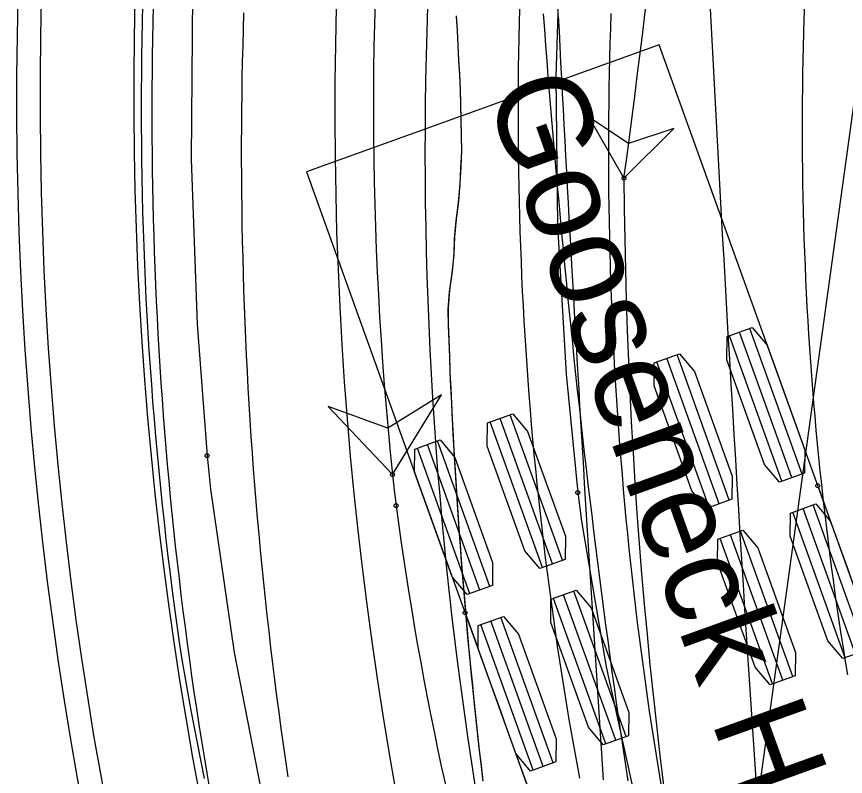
# Model space of a CAD drawing. Extents: x -14 to 1565148, y -25 to 642856.
# Drawn here: x 1564752.49 to 1564770.18, y 636470.57 to 636486.78 of the extents above; entities that cross this region are included whole.
import ezdxf

# ---------------------------------------------------------------- set-up
doc = ezdxf.new("R2010")
doc.units = 0
for name, color, linetype in [('CM_Corridor_Conceptual', 7, 'Continuous'), ('DR_P_Headwall', 7, 'Continuous'), ('GE_P_Alignment_100_Stations', 7, 'Continuous'), ('PV_P_EOP', 7, 'Continuous'), ('PV_X_EOP', 7, 'Continuous'), ('TR_Turning_Path22', 7, 'Continuous'), ('TR_Turning_Path28', 7, 'Continuous'), ('TR_Turning_Path28 - Copy-1', 7, 'Continuous')]:
    doc.layers.add(name, color=color, linetype=linetype)

msp = doc.modelspace()

# ---------------------------------------------------------------- linework, layer by layer
at = {"layer": 'CM_Corridor_Conceptual'}
for p, q in [((1564766.204, 636486.176), (1564758.676, 636483.468)), ((1564778.392, 636452.302), (1564766.204, 636486.176)), ((1564758.676, 636483.468), (1564770.864, 636449.594)), ((1564769.255, 636477.018), (1564768.138, 636480.123)), ((1564768.824, 636476.863), (1564767.707, 636479.968)), ((1564769.039, 636476.941), (1564767.922, 636480.046)), ((1564767.702, 636476.46), (1564766.585, 636479.565)), ((1564767.271, 636476.305), (1564766.154, 636479.41)), ((1564767.487, 636476.382), (1564766.37, 636479.487)), ((1564763.711, 636475.024), (1564762.594, 636478.129)), ((1564763.927, 636475.101), (1564762.81, 636478.206)), ((1564764.143, 636475.179), (1564763.025, 636478.284)), ((1564762.374, 636474.543), (1564761.257, 636477.648)), ((1564762.59, 636474.62), (1564761.473, 636477.725)), ((1564762.159, 636474.465), (1564761.042, 636477.57)), ((1564770.609, 636473.255), (1564769.492, 636476.36)), ((1564770.178, 636473.099), (1564769.061, 636476.204)), ((1564770.394, 636473.177), (1564769.276, 636476.282)), ((1564768.625, 636472.541), (1564767.508, 636475.646)), ((1564768.841, 636472.618), (1564767.724, 636475.723)), ((1564769.057, 636472.696), (1564767.939, 636475.801)), ((1564765.281, 636471.337), (1564764.164, 636474.443)), ((1564765.497, 636471.415), (1564764.38, 636474.52)), ((1564765.066, 636471.26), (1564763.948, 636474.365)), ((1564763.729, 636470.779), (1564762.611, 636473.884)), ((1564763.944, 636470.856), (1564762.827, 636473.962)), ((1564763.513, 636470.701), (1564762.396, 636473.806))]:
    msp.add_line(p, q, dxfattribs=at)
for points in [[(1564769.309, 636477.038), (1564768.77, 636476.844), (1564768.452, 636477.22), (1564767.647, 636479.456), (1564767.653, 636479.949), (1564768.191, 636480.143), (1564768.51, 636479.766), (1564769.314, 636477.531)], [(1564767.756, 636476.479), (1564767.218, 636476.285), (1564766.899, 636476.662), (1564766.095, 636478.897), (1564766.101, 636479.39), (1564766.639, 636479.584), (1564766.957, 636479.208), (1564767.762, 636476.972)], [(1564764.196, 636475.198), (1564763.658, 636475.004), (1564763.339, 636475.381), (1564762.535, 636477.616), (1564762.541, 636478.11), (1564763.079, 636478.303), (1564763.397, 636477.927), (1564764.202, 636475.691)], [(1564762.644, 636474.639), (1564762.105, 636474.446), (1564761.787, 636474.822), (1564760.982, 636477.058), (1564760.988, 636477.551), (1564761.526, 636477.745), (1564761.845, 636477.368), (1564762.649, 636475.133)], [(1564770.663, 636473.274), (1564770.125, 636473.08), (1564769.806, 636473.456), (1564769.002, 636475.692), (1564769.007, 636476.185), (1564769.546, 636476.379), (1564769.864, 636476.003), (1564770.669, 636473.767)], [(1564769.11, 636472.715), (1564768.572, 636472.521), (1564768.253, 636472.898), (1564767.449, 636475.134), (1564767.455, 636475.627), (1564767.993, 636475.82), (1564768.312, 636475.444), (1564769.116, 636473.208)], [(1564765.55, 636471.434), (1564765.012, 636471.241), (1564764.693, 636471.617), (1564763.889, 636473.853), (1564763.895, 636474.346), (1564764.433, 636474.539), (1564764.752, 636474.163), (1564765.556, 636471.927)], [(1564763.998, 636470.876), (1564763.46, 636470.682), (1564763.141, 636471.058), (1564762.337, 636473.294), (1564762.342, 636473.787), (1564762.88, 636473.981), (1564763.199, 636473.604), (1564764.003, 636471.369)]]:
    msp.add_lwpolyline(points, close=True, dxfattribs=at)
for points in [[(1564769.589, 636476.767), (1564769.702, 636476.454), (1564769.814, 636476.141), (1564769.927, 636475.828), (1564770.039, 636475.515), (1564770.152, 636475.202), (1564770.265, 636474.89)], [(1564762.062, 636474.058), (1564762.174, 636473.745), (1564762.287, 636473.432), (1564762.399, 636473.12), (1564762.512, 636472.807), (1564762.624, 636472.494), (1564762.737, 636472.181), (1564762.85, 636471.868), (1564762.962, 636471.555), (1564763.075, 636471.242), (1564763.187, 636470.93), (1564763.3, 636470.617), (1564763.413, 636470.304)]]:
    msp.add_lwpolyline(points, dxfattribs=at)
for centre in [(1564769.589, 636476.767), (1564762.062, 636474.058)]:
    msp.add_circle(centre, 0.0417, dxfattribs=at)
at = {"layer": 'DR_P_Headwall'}
for points in [[(1564762.441, 636470.512), (1564762.403, 636470.845), (1564762.365, 636471.177), (1564762.328, 636471.51), (1564762.292, 636471.843), (1564762.257, 636472.177), (1564762.223, 636472.51), (1564762.19, 636472.844), (1564762.158, 636473.178), (1564762.126, 636473.513), (1564762.096, 636473.847), (1564762.067, 636474.182), (1564762.039, 636474.516), (1564762.011, 636474.851), (1564761.985, 636475.186), (1564761.96, 636475.521), (1564761.935, 636475.857), (1564761.912, 636476.192), (1564761.889, 636476.528), (1564761.868, 636476.863), (1564761.847, 636477.199), (1564761.828, 636477.535), (1564761.809, 636477.87), (1564761.792, 636478.206), (1564761.775, 636478.542), (1564761.76, 636478.878), (1564761.745, 636479.214), (1564761.732, 636479.549), (1564761.719, 636479.885), (1564761.707, 636480.221), (1564761.708, 636480.567), (1564761.739, 636480.944), (1564761.79, 636481.341), (1564761.826, 636481.72), (1564761.84, 636482.076), (1564761.876, 636482.453), (1564761.925, 636482.842), (1564761.957, 636483.213), (1564761.976, 636483.569), (1564761.991, 636483.92), (1564761.985, 636484.249), (1564761.98, 636484.579), (1564761.973, 636484.906), (1564761.962, 636485.227), (1564761.947, 636485.544), (1564761.931, 636485.858), (1564761.914, 636486.171), (1564761.897, 636486.483), (1564761.879, 636486.793)], [(1564762.447, 636470.464), (1564762.408, 636470.797), (1564762.37, 636471.13), (1564762.333, 636471.463), (1564762.297, 636471.797), (1564762.261, 636472.131), (1564762.227, 636472.465), (1564762.194, 636472.799), (1564762.162, 636473.134), (1564762.13, 636473.469), (1564762.1, 636473.804), (1564762.07, 636474.139), (1564762.042, 636474.474), (1564762.015, 636474.809), (1564761.988, 636475.145), (1564761.962, 636475.481), (1564761.938, 636475.817), (1564761.914, 636476.153), (1564761.892, 636476.489), (1564761.87, 636476.825), (1564761.85, 636477.161), (1564761.83, 636477.498), (1564761.811, 636477.834), (1564761.794, 636478.171), (1564761.777, 636478.507), (1564761.761, 636478.843), (1564761.746, 636479.18), (1564761.733, 636479.517), (1564761.72, 636479.853), (1564761.708, 636480.189), (1564761.698, 636480.527), (1564761.731, 636480.906), (1564761.786, 636481.307), (1564761.828, 636481.693), (1564761.836, 636482.045), (1564761.871, 636482.422), (1564761.923, 636482.814), (1564761.957, 636483.188), (1564761.972, 636483.542), (1564761.991, 636483.898), (1564761.985, 636484.229), (1564761.98, 636484.559), (1564761.973, 636484.887), (1564761.962, 636485.21), (1564761.948, 636485.528), (1564761.931, 636485.844), (1564761.915, 636486.158), (1564761.897, 636486.472), (1564761.879, 636486.783)], [(1564765.453, 636483.33), (1564766.516, 636484.388), (1564765.552, 636484.073), (1564764.706, 636484.631), (1564765.453, 636483.33)]]:
    msp.add_lwpolyline(points, dxfattribs=at)
msp.add_lwpolyline([(1564765.453, 636483.33), (1564766.516, 636484.388), (1564765.552, 636484.073), (1564764.706, 636484.631)], close=True, dxfattribs=at)
msp.add_circle((1564765.453, 636483.33), 0.0417, dxfattribs=at)
msp.add_circle((1564765.453, 636483.33), 0.0417, dxfattribs=at)
for centre, radius, start, end in [((1564504.01, 636518.53), 263.802, 352.33185, 358.4354), ((1564877.338, 636484.105), 111.888, 180.39704, 201.6728)]:
    msp.add_arc(centre, radius, start, end, dxfattribs=at)
at = {"layer": 'GE_P_Alignment_100_Stations'}
msp.add_line((1564772.301, 636499.036), (1564765.743, 636451.487), dxfattribs=at)
for points in [[(1564756.72, 636493.911), (1564756.427, 636490.771), (1564756.241, 636487.255), (1564756.212, 636483.734), (1564756.339, 636480.216), (1564756.554, 636477.407)], [(1564764.303, 636491.539), (1564764.097, 636488.674), (1564763.996, 636485.499), (1564764.037, 636482.323), (1564764.219, 636479.152), (1564764.466, 636476.623)], [(1564756.497, 636470.522), (1564756.424, 636470.884), (1564756.353, 636471.246), (1564756.283, 636471.609), (1564756.216, 636471.972), (1564756.15, 636472.335), (1564756.086, 636472.699), (1564756.024, 636473.063), (1564755.967, 636473.428), (1564755.914, 636473.793), (1564755.865, 636474.158), (1564755.817, 636474.524), (1564755.77, 636474.89), (1564755.725, 636475.256), (1564755.682, 636475.623), (1564755.641, 636475.989), (1564755.601, 636476.356), (1564755.563, 636476.722), (1564755.527, 636477.089), (1564755.492, 636477.456), (1564755.459, 636477.824), (1564755.428, 636478.191), (1564755.398, 636478.559), (1564755.371, 636478.926), (1564755.344, 636479.294), (1564755.32, 636479.662), (1564755.297, 636480.03), (1564755.276, 636480.398), (1564755.256, 636480.766), (1564755.239, 636481.134), (1564755.223, 636481.502), (1564755.208, 636481.87), (1564755.195, 636482.239), (1564755.184, 636482.607), (1564755.175, 636482.975), (1564755.168, 636483.344), (1564755.162, 636483.712), (1564755.157, 636484.081), (1564755.155, 636484.449), (1564755.154, 636484.818), (1564755.155, 636485.186), (1564755.157, 636485.555), (1564755.162, 636485.923), (1564755.167, 636486.291), (1564755.175, 636486.66), (1564755.184, 636487.028)], [(1564760.511, 636477.005), (1564761.561, 636478.708), (1564760.409, 636478), (1564759.138, 636478.46), (1564760.511, 636477.005)], [(1564756.553, 636477.408), (1564756.629, 636476.696), (1564757.134, 636473.208), (1564757.805, 636469.75), (1564758.638, 636466.328), (1564759.633, 636462.95), (1564760.788, 636459.622), (1564762.1, 636456.353), (1564763.565, 636453.15), (1564763.876, 636452.518)], [(1564760.511, 636477.005), (1564760.546, 636476.674), (1564760.588, 636476.343)], [(1564764.466, 636476.622), (1564764.545, 636476.012), (1564765.072, 636472.905), (1564765.748, 636469.823), (1564766.569, 636466.777), (1564767.534, 636463.773), (1564768.641, 636460.819), (1564769.887, 636457.921), (1564771.269, 636455.086), (1564771.561, 636454.527)]]:
    msp.add_lwpolyline(points, dxfattribs=at)
msp.add_lwpolyline([(1564760.511, 636477.005), (1564761.561, 636478.708), (1564760.409, 636478), (1564759.138, 636478.46)], close=True, dxfattribs=at)
for centre in [(1564756.553, 636477.408), (1564756.554, 636477.407), (1564760.511, 636477.005), (1564760.511, 636477.005), (1564764.466, 636476.623), (1564764.466, 636476.622), (1564760.588, 636476.343), (1564760.588, 636476.343)]:
    msp.add_circle(centre, 0.0417, dxfattribs=at)
for centre, radius, start, end in [((1564835.491, 636484.834), 75.387, 174.25352, 185.96071), ((1564830.196, 636485.568), 70.216, 187.54952, 207.16349)]:
    msp.add_arc(centre, radius, start, end, dxfattribs=at)
at = {"layer": 'PV_P_EOP'}
for radius in [82.5, 82]:
    msp.add_arc((1564834.986, 636485.101), radius, 163.93404, 201.28998, dxfattribs=at)
at = {"layer": 'PV_X_EOP'}
msp.add_arc((1564834.986, 636485.101), 80, 163.93389, 201.28998, dxfattribs=at)
at = {"layer": 'TR_Turning_Path22'}
for points in [[(1564763.727, 636486.839), (1564763.753, 636486.504), (1564763.778, 636486.169), (1564763.805, 636485.834), (1564763.831, 636485.5), (1564763.858, 636485.165), (1564763.885, 636484.83), (1564763.913, 636484.495), (1564763.942, 636484.161), (1564763.97, 636483.826), (1564763.999, 636483.491), (1564764.029, 636483.157), (1564764.059, 636482.822), (1564764.09, 636482.487), (1564764.121, 636482.153), (1564764.152, 636481.818), (1564764.184, 636481.484), (1564764.216, 636481.149), (1564764.249, 636480.815), (1564764.283, 636480.48), (1564764.317, 636480.146), (1564764.351, 636479.812), (1564764.386, 636479.477), (1564764.421, 636479.143), (1564764.457, 636478.809), (1564764.494, 636478.475), (1564764.531, 636478.141), (1564764.568, 636477.806), (1564764.606, 636477.472), (1564764.645, 636477.138), (1564764.684, 636476.805), (1564764.723, 636476.471), (1564764.764, 636476.137), (1564764.804, 636475.803), (1564764.846, 636475.469), (1564764.887, 636475.136), (1564764.93, 636474.802), (1564764.973, 636474.469), (1564765.016, 636474.135), (1564765.06, 636473.802), (1564765.105, 636473.469), (1564765.15, 636473.135), (1564765.196, 636472.802), (1564765.242, 636472.469), (1564765.289, 636472.136), (1564765.337, 636471.803), (1564765.385, 636471.471), (1564765.434, 636471.138), (1564765.483, 636470.805), (1564765.533, 636470.473)], [(1564764.049, 636486.797), (1564764.066, 636486.465), (1564764.083, 636486.132), (1564764.1, 636485.799), (1564764.117, 636485.466), (1564764.135, 636485.133), (1564764.153, 636484.8), (1564764.17, 636484.468), (1564764.188, 636484.135), (1564764.206, 636483.802), (1564764.224, 636483.469), (1564764.242, 636483.136), (1564764.26, 636482.804), (1564764.279, 636482.471), (1564764.297, 636482.138), (1564764.316, 636481.805), (1564764.334, 636481.472), (1564764.353, 636481.14), (1564764.372, 636480.807), (1564764.391, 636480.474), (1564764.41, 636480.141), (1564764.429, 636479.809), (1564764.448, 636479.476), (1564764.468, 636479.143), (1564764.487, 636478.811), (1564764.507, 636478.478), (1564764.526, 636478.145), (1564764.546, 636477.812), (1564764.566, 636477.48), (1564764.586, 636477.147), (1564764.606, 636476.814), (1564764.627, 636476.482), (1564764.647, 636476.149), (1564764.667, 636475.816), (1564764.688, 636475.484), (1564764.709, 636475.151), (1564764.729, 636474.818), (1564764.75, 636474.486), (1564764.771, 636474.153), (1564764.792, 636473.821), (1564764.814, 636473.488), (1564764.835, 636473.155), (1564764.856, 636472.823), (1564764.878, 636472.49), (1564764.899, 636472.158), (1564764.921, 636471.825), (1564764.943, 636471.492), (1564764.965, 636471.16), (1564764.987, 636470.827), (1564765.009, 636470.495)]]:
    msp.add_lwpolyline(points, dxfattribs=at)
msp.add_arc((1565807.83, 636540.104), 1041.892, 182.395523, 184.277468, dxfattribs=at)
at = {"layer": 'TR_Turning_Path28'}
for points in [[(1564755.405, 636486.997), (1564755.397, 636486.648), (1564755.389, 636486.299), (1564755.383, 636485.949), (1564755.379, 636485.6), (1564755.376, 636485.25), (1564755.374, 636484.901), (1564755.374, 636484.551), (1564755.376, 636484.202), (1564755.378, 636483.853), (1564755.383, 636483.503), (1564755.388, 636483.154), (1564755.395, 636482.804), (1564755.404, 636482.455), (1564755.414, 636482.106), (1564755.425, 636481.757), (1564755.438, 636481.407), (1564755.452, 636481.058), (1564755.468, 636480.709), (1564755.485, 636480.36), (1564755.504, 636480.011), (1564755.524, 636479.662), (1564755.545, 636479.314), (1564755.568, 636478.965), (1564755.592, 636478.616), (1564755.618, 636478.268), (1564755.645, 636477.919), (1564755.674, 636477.571), (1564755.704, 636477.223), (1564755.735, 636476.875), (1564755.768, 636476.527), (1564755.802, 636476.179), (1564755.838, 636475.832), (1564755.875, 636475.484), (1564755.914, 636475.137), (1564755.954, 636474.79), (1564755.995, 636474.443), (1564756.038, 636474.096), (1564756.082, 636473.749), (1564756.128, 636473.403), (1564756.175, 636473.057), (1564756.224, 636472.711), (1564756.274, 636472.365), (1564756.325, 636472.019), (1564756.378, 636471.674), (1564756.432, 636471.328), (1564756.488, 636470.983), (1564756.545, 636470.639), (1564756.603, 636470.294)], [(1564769.307, 636487.016), (1564769.296, 636486.724), (1564769.287, 636486.431), (1564769.28, 636486.139), (1564769.273, 636485.846), (1564769.267, 636485.554), (1564769.263, 636485.261), (1564769.26, 636484.969), (1564769.258, 636484.676), (1564769.258, 636484.384), (1564769.258, 636484.091), (1564769.26, 636483.799), (1564769.263, 636483.506), (1564769.267, 636483.214), (1564769.273, 636482.921), (1564769.28, 636482.629), (1564769.287, 636482.336), (1564769.296, 636482.044), (1564769.307, 636481.752), (1564769.318, 636481.459), (1564769.331, 636481.167), (1564769.345, 636480.875), (1564769.36, 636480.583), (1564769.376, 636480.29), (1564769.394, 636479.998), (1564769.413, 636479.706), (1564769.433, 636479.415), (1564769.454, 636479.123), (1564769.476, 636478.831), (1564769.5, 636478.539), (1564769.525, 636478.248), (1564769.551, 636477.956), (1564769.578, 636477.665), (1564769.606, 636477.374), (1564769.636, 636477.083), (1564769.667, 636476.792), (1564769.699, 636476.501), (1564769.732, 636476.21), (1564769.766, 636475.919), (1564769.802, 636475.629), (1564769.839, 636475.339), (1564769.877, 636475.048), (1564769.916, 636474.758), (1564769.957, 636474.469), (1564769.998, 636474.179), (1564770.041, 636473.889), (1564770.085, 636473.6), (1564770.13, 636473.311), (1564770.177, 636473.022), (1564770.225, 636472.733)], [(1564763.224, 636486.951), (1564763.215, 636486.634), (1564763.208, 636486.317), (1564763.202, 636485.999), (1564763.197, 636485.682), (1564763.194, 636485.365), (1564763.192, 636485.047), (1564763.191, 636484.73), (1564763.191, 636484.413), (1564763.193, 636484.095), (1564763.196, 636483.778), (1564763.201, 636483.46), (1564763.206, 636483.143), (1564763.213, 636482.826), (1564763.222, 636482.509), (1564763.231, 636482.191), (1564763.242, 636481.874), (1564763.255, 636481.557), (1564763.268, 636481.24), (1564763.283, 636480.923), (1564763.299, 636480.606), (1564763.317, 636480.289), (1564763.335, 636479.972), (1564763.356, 636479.656), (1564763.377, 636479.339), (1564763.4, 636479.023), (1564763.424, 636478.706), (1564763.449, 636478.39), (1564763.475, 636478.074), (1564763.503, 636477.757), (1564763.532, 636477.441), (1564763.563, 636477.126), (1564763.595, 636476.81), (1564763.628, 636476.494), (1564763.662, 636476.179), (1564763.698, 636475.863), (1564763.735, 636475.548), (1564763.773, 636475.233), (1564763.813, 636474.918), (1564763.853, 636474.604), (1564763.896, 636474.289), (1564763.939, 636473.975), (1564763.984, 636473.66), (1564764.03, 636473.346), (1564764.077, 636473.033), (1564764.126, 636472.719), (1564764.176, 636472.406), (1564764.227, 636472.092), (1564764.279, 636471.779), (1564764.333, 636471.467), (1564764.388, 636471.154), (1564764.444, 636470.842), (1564764.502, 636470.53)]]:
    msp.add_lwpolyline(points, dxfattribs=at)
msp.add_arc((1564840.393, 636484.698), 81.107, 162.2375, 235.00942, dxfattribs=at)
at = {"layer": 'TR_Turning_Path28 - Copy-1'}
for points in [[(1564757.333, 636486.857), (1564757.322, 636486.509), (1564757.313, 636486.161), (1564757.305, 636485.814), (1564757.298, 636485.466), (1564757.292, 636485.118), (1564757.288, 636484.77), (1564757.286, 636484.422), (1564757.284, 636484.075), (1564757.284, 636483.727), (1564757.286, 636483.379), (1564757.288, 636483.031), (1564757.292, 636482.683), (1564757.298, 636482.336), (1564757.304, 636481.988), (1564757.313, 636481.64), (1564757.322, 636481.292), (1564757.333, 636480.945), (1564757.345, 636480.597), (1564757.358, 636480.25), (1564757.373, 636479.902), (1564757.389, 636479.555), (1564757.406, 636479.207), (1564757.425, 636478.86), (1564757.445, 636478.513), (1564757.467, 636478.166), (1564757.49, 636477.819), (1564757.514, 636477.472), (1564757.539, 636477.125), (1564757.566, 636476.778), (1564757.594, 636476.431), (1564757.624, 636476.085), (1564757.655, 636475.738), (1564757.687, 636475.392), (1564757.72, 636475.046), (1564757.755, 636474.7), (1564757.791, 636474.354), (1564757.829, 636474.008), (1564757.868, 636473.662), (1564757.908, 636473.317), (1564757.95, 636472.971), (1564757.992, 636472.626), (1564758.037, 636472.281), (1564758.082, 636471.936), (1564758.129, 636471.592), (1564758.177, 636471.247), (1564758.227, 636470.903), (1564758.278, 636470.559)], [(1564765.175, 636486.843), (1564765.164, 636486.526), (1564765.154, 636486.209), (1564765.146, 636485.891), (1564765.139, 636485.574), (1564765.133, 636485.256), (1564765.128, 636484.939), (1564765.125, 636484.621), (1564765.123, 636484.303), (1564765.122, 636483.986), (1564765.122, 636483.668), (1564765.123, 636483.351), (1564765.126, 636483.033), (1564765.13, 636482.716), (1564765.135, 636482.398), (1564765.142, 636482.081), (1564765.149, 636481.763), (1564765.158, 636481.446), (1564765.168, 636481.128), (1564765.18, 636480.811), (1564765.192, 636480.494), (1564765.206, 636480.176), (1564765.221, 636479.859), (1564765.237, 636479.542), (1564765.254, 636479.225), (1564765.273, 636478.908), (1564765.293, 636478.591), (1564765.314, 636478.274), (1564765.336, 636477.957), (1564765.36, 636477.64), (1564765.385, 636477.324), (1564765.411, 636477.007), (1564765.438, 636476.691), (1564765.466, 636476.375), (1564765.496, 636476.058), (1564765.527, 636475.742), (1564765.559, 636475.426), (1564765.592, 636475.111), (1564765.627, 636474.795), (1564765.663, 636474.479), (1564765.7, 636474.164), (1564765.738, 636473.849), (1564765.777, 636473.534), (1564765.818, 636473.219), (1564765.86, 636472.904), (1564765.903, 636472.589), (1564765.947, 636472.275), (1564765.993, 636471.961), (1564766.039, 636471.646), (1564766.087, 636471.332), (1564766.137, 636471.019), (1564766.187, 636470.705), (1564766.238, 636470.392)]]:
    msp.add_lwpolyline(points, dxfattribs=at)
msp.add_arc((1564847.314, 636483.896), 86.109, 162.1862, 206.90212, dxfattribs=at)

# ---------------------------------------------------------------- texts
at = {"layer": 'CM_Corridor_Conceptual'}
msp.add_text('Gooseneck Horse Trailer', height=2, rotation=289.7889, dxfattribs=at).set_placement((1564762.478, 636485.19))

doc.saveas('drawing.dxf')
